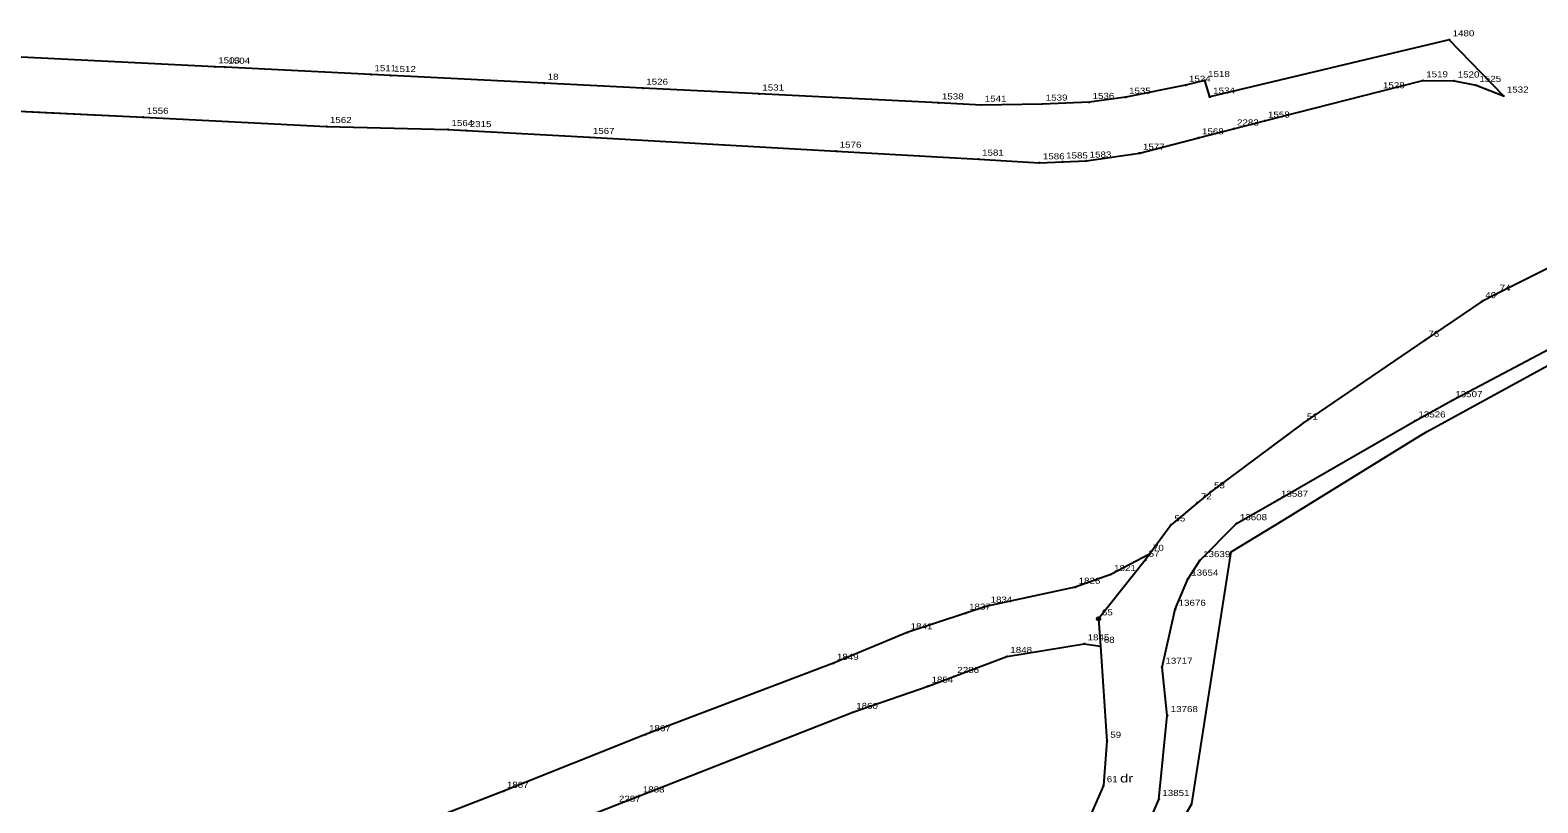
# Model space of a CAD drawing. Extents: x 4640203 to 4644676, y 5358265 to 5360852.
# Drawn here: x 4641404.9 to 4641627.9, y 5359948.6 to 5360062.9 of the extents above; entities that cross this region are included whole.
import ezdxf

# ---------------------------------------------------------------- set-up
doc = ezdxf.new("R2010")
doc.units = 0
doc.header["$LTSCALE"] = 0.36
for name, color, linetype, lineweight in [('25', 7, 'Continuous', 25), ('27', 7, 'Continuous', 25), ('8', 7, 'Continuous', 25)]:
    doc.layers.add(name, color=color, linetype=linetype, lineweight=lineweight)
doc.layers.add('26', color=7, linetype='Continuous')

msp = doc.modelspace()

# ---------------------------------------------------------------- linework, layer by layer
at = {"layer": '25'}
for points in [[(4641398.17, 5360051.22), (4641421.7, 5360050.05), (4641448.78, 5360048.69), (4641466.76, 5360048.24), (4641469.46, 5360048.09), (4641487.67, 5360047.08), (4641524.18, 5360045.04), (4641545.24, 5360043.87), (4641554.23, 5360043.32), (4641557.67, 5360043.45), (4641561.15, 5360043.58), (4641569.03, 5360044.74), (4641577.77, 5360047.01), (4641582.95, 5360048.33), (4641587.52, 5360049.5), (4641604.53, 5360053.84), (4641610.93, 5360055.47), (4641615.59, 5360055.43), (4641618.8, 5360054.78), (4641622.86, 5360053.2), (4641614.84, 5360061.53), (4641579.42, 5360053.05), (4641578.67, 5360055.5), (4641575.84, 5360054.8), (4641566.98, 5360053.02), (4641561.58, 5360052.26), (4641554.66, 5360052.01), (4641545.64, 5360051.86), (4641539.3, 5360052.18), (4641512.74, 5360053.5), (4641495.57, 5360054.36), (4641480.99, 5360055.09), (4641458.28, 5360056.23), (4641455.37, 5360056.37), (4641433.76, 5360057.47), (4641432.26, 5360057.53), (4641398.61, 5360059.21)], [(4641638.62, 5360032.31), (4641621.79, 5360023.85), (4641619.67, 5360022.78), (4641611.25, 5360017.05), (4641593.27, 5360004.81), (4641579.55, 5359994.63), (4641577.6, 5359993), (4641573.69, 5359989.73), (4641570.51, 5359985.37), (4641569.88, 5359984.5), (4641562.96, 5359975.83)], [(4641393.23, 5359829.23), (4641419.21, 5359842), (4641450.45, 5359856.65), (4641485.58, 5359875.36), (4641510.9, 5359889.97), (4641524.31, 5359900.25), (4641540.6, 5359913.36), (4641543.14, 5359915.05), (4641564.28, 5359934.14), (4641570.79, 5359940.48), (4641568.84, 5359941.93), (4641571.9, 5359949.1), (4641573.14, 5359961.51), (4641572.36, 5359968.66), (4641574.31, 5359977.24), (4641576.17, 5359981.71), (4641577.93, 5359984.45), (4641583.37, 5359989.91), (4641589.45, 5359993.38), (4641609.78, 5360005.12), (4641615.23, 5360008.12), (4641645.61, 5360024.19)], [(4641570.51, 5359985.37), (4641564.77, 5359982.39), (4641559.52, 5359980.5), (4641546.5, 5359977.71), (4641543.32, 5359976.67), (4641534.67, 5359973.77), (4641523.77, 5359969.24), (4641495.98, 5359958.68), (4641474.96, 5359950.3), (4641460.37, 5359944.64), (4641457.31, 5359943.44), (4641456.45, 5359943.13), (4641457.31, 5359940.89), (4641427.95, 5359929.83), (4641427.09, 5359932.27), (4641424.73, 5359931.44), (4641412.06, 5359927.34), (4641405.03, 5359926.16), (4641400.29, 5359925.36)], [(4641562.96, 5359975.83), (4641563.24, 5359971.76), (4641564.2, 5359957.7), (4641563.68, 5359951.14), (4641560.37, 5359943.49), (4641556.06, 5359939.38), (4641535.84, 5359920.89), (4641522.24, 5359909.8), (4641520.76, 5359908.59), (4641519.54, 5359907.82), (4641518.21, 5359906.97), (4641495.52, 5359892.68), (4641490.9, 5359889.77), (4641474.14, 5359879.72), (4641456.27, 5359868.99), (4641442.71, 5359862.24), (4641436.79, 5359859.29), (4641405.9, 5359845.24), (4641404.44, 5359844.57)], [(4641401.25, 5359917.1), (4641412.03, 5359918.91), (4641415.15, 5359919.43), (4641422.09, 5359921.79), (4641427.76, 5359923.72), (4641444.68, 5359930.01), (4641461.9, 5359936.65), (4641463.29, 5359937.19), (4641469.81, 5359939.74), (4641471.39, 5359940.36), (4641491.52, 5359948.24), (4641495.05, 5359949.62), (4641526.62, 5359961.98), (4641537.77, 5359965.86), (4641541.58, 5359967.3), (4641549.42, 5359970.26), (4641560.85, 5359972.13), (4641563.24, 5359971.76)]]:
    msp.add_lwpolyline(points, dxfattribs=at)
at = {"layer": '27'}
for points in [[(4641398.17, 5360051.22), (4641407.16, 5360050.77), (4641421.7, 5360050.05), (4641448.78, 5360048.69), (4641466.76, 5360048.24), (4641469.46, 5360048.09), (4641487.67, 5360047.08), (4641524.18, 5360045.04), (4641545.24, 5360043.87), (4641554.23, 5360043.32), (4641557.67, 5360043.45), (4641561.15, 5360043.58), (4641569.03, 5360044.74), (4641577.77, 5360047.01), (4641582.95, 5360048.33), (4641587.52, 5360049.5), (4641604.53, 5360053.84), (4641610.93, 5360055.47), (4641615.59, 5360055.43), (4641618.8, 5360054.78), (4641622.86, 5360053.2), (4641614.84, 5360061.53), (4641579.42, 5360053.05), (4641578.67, 5360055.5), (4641575.84, 5360054.8), (4641566.98, 5360053.02), (4641561.58, 5360052.26), (4641554.66, 5360052.01), (4641545.64, 5360051.86), (4641539.3, 5360052.18), (4641512.74, 5360053.5), (4641495.57, 5360054.36), (4641480.99, 5360055.09), (4641458.28, 5360056.23), (4641455.37, 5360056.37), (4641433.76, 5360057.47), (4641432.26, 5360057.53), (4641398.61, 5360059.21)], [(4641638.62, 5360032.31), (4641621.79, 5360023.85), (4641619.67, 5360022.78), (4641611.25, 5360017.05), (4641593.27, 5360004.81), (4641579.55, 5359994.63), (4641577.6, 5359993), (4641573.69, 5359989.73), (4641570.51, 5359985.37), (4641569.88, 5359984.5), (4641562.96, 5359975.83), (4641563.24, 5359971.76)], [(4641377.28, 5359814.48), (4641416.25, 5359834.78), (4641434.46, 5359844.26), (4641458.97, 5359856.72), (4641463.02, 5359858.78), (4641504.18, 5359882.87), (4641521.98, 5359893.29), (4641552.82, 5359920.25), (4641551.9, 5359921.57), (4641557.11, 5359925.08), (4641557.57, 5359924.41), (4641568.08, 5359933.61), (4641576.75, 5359948.43), (4641582.6, 5359985.72), (4641590.35, 5359990.49), (4641610.5, 5360002.89), (4641611.56, 5360003.54), (4641644.63, 5360021.64)], [(4641570.51, 5359985.37), (4641564.77, 5359982.39), (4641559.52, 5359980.5), (4641546.5, 5359977.71), (4641543.32, 5359976.67), (4641534.67, 5359973.77), (4641523.77, 5359969.24), (4641495.98, 5359958.68), (4641474.96, 5359950.3), (4641460.37, 5359944.64), (4641457.31, 5359943.44), (4641456.45, 5359943.13), (4641441.76, 5359937.46), (4641427.09, 5359932.27), (4641424.73, 5359931.44), (4641412.06, 5359927.34), (4641405.03, 5359926.16), (4641400.29, 5359925.36)], [(4641491.52, 5359948.24), (4641495.05, 5359949.62), (4641526.62, 5359961.98), (4641537.77, 5359965.86), (4641541.58, 5359967.3), (4641549.42, 5359970.26), (4641560.85, 5359972.13), (4641563.24, 5359971.76)], [(4641563.24, 5359971.76), (4641564.2, 5359957.7), (4641563.68, 5359951.14), (4641560.37, 5359943.49), (4641556.06, 5359939.38), (4641535.84, 5359920.89), (4641522.24, 5359909.8), (4641520.76, 5359908.59), (4641519.54, 5359907.82)]]:
    msp.add_lwpolyline(points, dxfattribs=at)
at = {"layer": '8'}
for centre, radius in [((4641614.84, 5360061.53), 0.045), ((4641432.26, 5360057.53), 0.045), ((4641433.76, 5360057.47), 0.045), ((4641455.37, 5360056.37), 0.045), ((4641458.28, 5360056.23), 0.045), ((4641480.99, 5360055.09), 0.045), ((4641578.67, 5360055.5), 0.045), ((4641610.93, 5360055.47), 0.045), ((4641615.59, 5360055.43), 0.045), ((4641495.57, 5360054.36), 0.045), ((4641512.74, 5360053.5), 0.045), ((4641566.98, 5360053.02), 0.045), ((4641575.84, 5360054.8), 0.045), ((4641579.42, 5360053.05), 0.045), ((4641604.53, 5360053.84), 0.045), ((4641618.8, 5360054.78), 0.045), ((4641622.86, 5360053.2), 0.045), ((4641539.3, 5360052.18), 0.045), ((4641545.64, 5360051.86), 0.045), ((4641554.66, 5360052.01), 0.045), ((4641561.58, 5360052.26), 0.045), ((4641421.7, 5360050.05), 0.045), ((4641448.78, 5360048.69), 0.045), ((4641466.76, 5360048.24), 0.045), ((4641582.95, 5360048.33), 0.045), ((4641587.52, 5360049.5), 0.045), ((4641469.46, 5360048.09), 0.045), ((4641487.67, 5360047.08), 0.045), ((4641577.77, 5360047.01), 0.045), ((4641524.18, 5360045.04), 0.045), ((4641545.24, 5360043.87), 0.045), ((4641569.03, 5360044.74), 0.045), ((4641554.23, 5360043.32), 0.045), ((4641557.67, 5360043.45), 0.045), ((4641561.15, 5360043.58), 0.045), ((4641621.79, 5360023.85), 0.045), ((4641619.67, 5360022.78), 0.045), ((4641611.25, 5360017.05), 0.045), ((4641615.23, 5360008.12), 0.045), ((4641593.27, 5360004.81), 0.045), ((4641609.78, 5360005.12), 0.045), ((4641577.6, 5359993), 0.045), ((4641579.55, 5359994.63), 0.045), ((4641589.45, 5359993.38), 0.045), ((4641573.69, 5359989.73), 0.045), ((4641583.37, 5359989.91), 0.045), ((4641569.88, 5359984.5), 0.045), ((4641570.51, 5359985.37), 0.045), ((4641577.93, 5359984.45), 0.045), ((4641564.77, 5359982.39), 0.045), ((4641576.17, 5359981.71), 0.045), ((4641559.52, 5359980.5), 0.045), ((4641546.5, 5359977.71), 0.045), ((4641574.31, 5359977.24), 0.045), ((4641543.32, 5359976.67), 0.045), ((4641562.96, 5359975.83), 0.25), ((4641534.67, 5359973.77), 0.045), ((4641549.42, 5359970.26), 0.045), ((4641560.85, 5359972.13), 0.045), ((4641563.24, 5359971.76), 0.045), ((4641523.77, 5359969.24), 0.045), ((4641572.36, 5359968.66), 0.045), ((4641537.77, 5359965.86), 0.045), ((4641541.58, 5359967.3), 0.045), ((4641526.62, 5359961.98), 0.045), ((4641573.14, 5359961.51), 0.045), ((4641495.98, 5359958.68), 0.045), ((4641564.2, 5359957.7), 0.045), ((4641474.96, 5359950.3), 0.045), ((4641563.68, 5359951.14), 0.045), ((4641495.05, 5359949.62), 0.045), ((4641571.9, 5359949.1), 0.045)]:
    msp.add_circle(centre, radius, dxfattribs=at)

# ---------------------------------------------------------------- texts
at = {"layer": '26', "width": 1.3}
msp.add_text('dr', height=1.25, dxfattribs=at).set_placement((4641566.15, 5359951.6))
at = {"layer": '8', "width": 1.2}
for s, p in [('1480', (4641615.34, 5360062.03)), ('1503', (4641432.76, 5360058.03)), ('1504', (4641434.26, 5360057.97)), ('1511', (4641455.87, 5360056.87)), ('1512', (4641458.78, 5360056.73)), ('18', (4641481.49, 5360055.59)), ('1526', (4641496.07, 5360054.86)), ('1524', (4641576.34, 5360055.3)), ('1518', (4641579.17, 5360056)), ('1528', (4641605.03, 5360054.34)), ('1519', (4641611.43, 5360055.97)), ('1520', (4641616.09, 5360055.93)), ('1525', (4641619.3, 5360055.28)), ('1531', (4641513.24, 5360054)), ('1538', (4641539.8, 5360052.68)), ('1541', (4641546.14, 5360052.36)), ('1539', (4641555.16, 5360052.51)), ('1536', (4641562.08, 5360052.76)), ('1535', (4641567.48, 5360053.52)), ('1534', (4641579.92, 5360053.55)), ('1532', (4641623.36, 5360053.7)), ('1556', (4641422.2, 5360050.55)), ('1558', (4641588.02, 5360050)), ('1562', (4641449.28, 5360049.19)), ('1564', (4641467.26, 5360048.74)), ('2315', (4641469.96, 5360048.59)), ('1567', (4641488.17, 5360047.58)), ('1568', (4641578.27, 5360047.51)), ('2283', (4641583.45, 5360048.83)), ('1576', (4641524.68, 5360045.54)), ('1577', (4641569.53, 5360045.24)), ('1581', (4641545.74, 5360044.37)), ('1586', (4641554.73, 5360043.82)), ('1585', (4641558.17, 5360043.95)), ('1583', (4641561.65, 5360044.08)), ('49', (4641620.17, 5360023.28)), ('74', (4641622.29, 5360024.35)), ('76', (4641611.75, 5360017.55)), ('13507', (4641615.73, 5360008.62)), ('51', (4641593.77, 5360005.31)), ('13526', (4641610.28, 5360005.62)), ('53', (4641580.05, 5359995.13)), ('13587', (4641589.95, 5359993.88)), ('72', (4641578.1, 5359993.5)), ('55', (4641574.19, 5359990.23)), ('13608', (4641583.87, 5359990.41)), ('57', (4641570.38, 5359985)), ('70', (4641571.01, 5359985.87)), ('13639', (4641578.43, 5359984.95)), ('1821', (4641565.27, 5359982.89)), ('1826', (4641560.02, 5359981)), ('13654', (4641576.67, 5359982.21)), ('1837', (4641543.82, 5359977.17)), ('1834', (4641547, 5359978.21)), ('65', (4641563.46, 5359976.33)), ('13676', (4641574.81, 5359977.74)), ('1841', (4641535.17, 5359974.27)), ('1845', (4641561.35, 5359972.63)), ('68', (4641563.74, 5359972.26)), ('1849', (4641524.27, 5359969.74)), ('1848', (4641549.92, 5359970.76)), ('2286', (4641542.08, 5359967.8)), ('13717', (4641572.86, 5359969.16)), ('1854', (4641538.27, 5359966.36)), ('1860', (4641527.12, 5359962.48)), ('13768', (4641573.64, 5359962.01)), ('1867', (4641496.48, 5359959.18)), ('59', (4641564.7, 5359958.2)), ('61', (4641564.18, 5359951.64)), ('1887', (4641475.46, 5359950.8)), ('1888', (4641495.55, 5359950.12)), ('13851', (4641572.4, 5359949.6)), ('2287', (4641492.02, 5359948.74))]:
    msp.add_text(s, height=0.9, dxfattribs=at).set_placement(p)

doc.saveas('drawing.dxf')
